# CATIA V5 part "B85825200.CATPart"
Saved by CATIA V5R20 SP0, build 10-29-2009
Part number: B85825200
Revision: 3
Definition: design
Nomenclature: B85825200
Source: made
Description: NOT SPECIFIED
Bounding box of the stored display mesh (mm): x -15 to 15, y -15 to 15, z 0 to 200
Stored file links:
  C:\Users\Raffaele\Desktop\3D X SITO CF\BOLEX\12-PILLAR REF 858\B85825200.CATPart
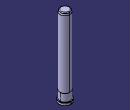
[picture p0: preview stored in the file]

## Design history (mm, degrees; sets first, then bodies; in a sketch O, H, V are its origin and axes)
Body1 "MANIFOLD_SOLID_BREP #450" (main body)
  Solid1: solid without history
